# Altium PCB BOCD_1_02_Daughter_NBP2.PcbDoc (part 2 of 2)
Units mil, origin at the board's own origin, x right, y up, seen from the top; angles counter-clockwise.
Board outline 2716.51 x 3188.78 mil, 2 copper layers (Top Layer, Bottom Layer); 52 components, 189 nets, 558 pads, 192 vias.
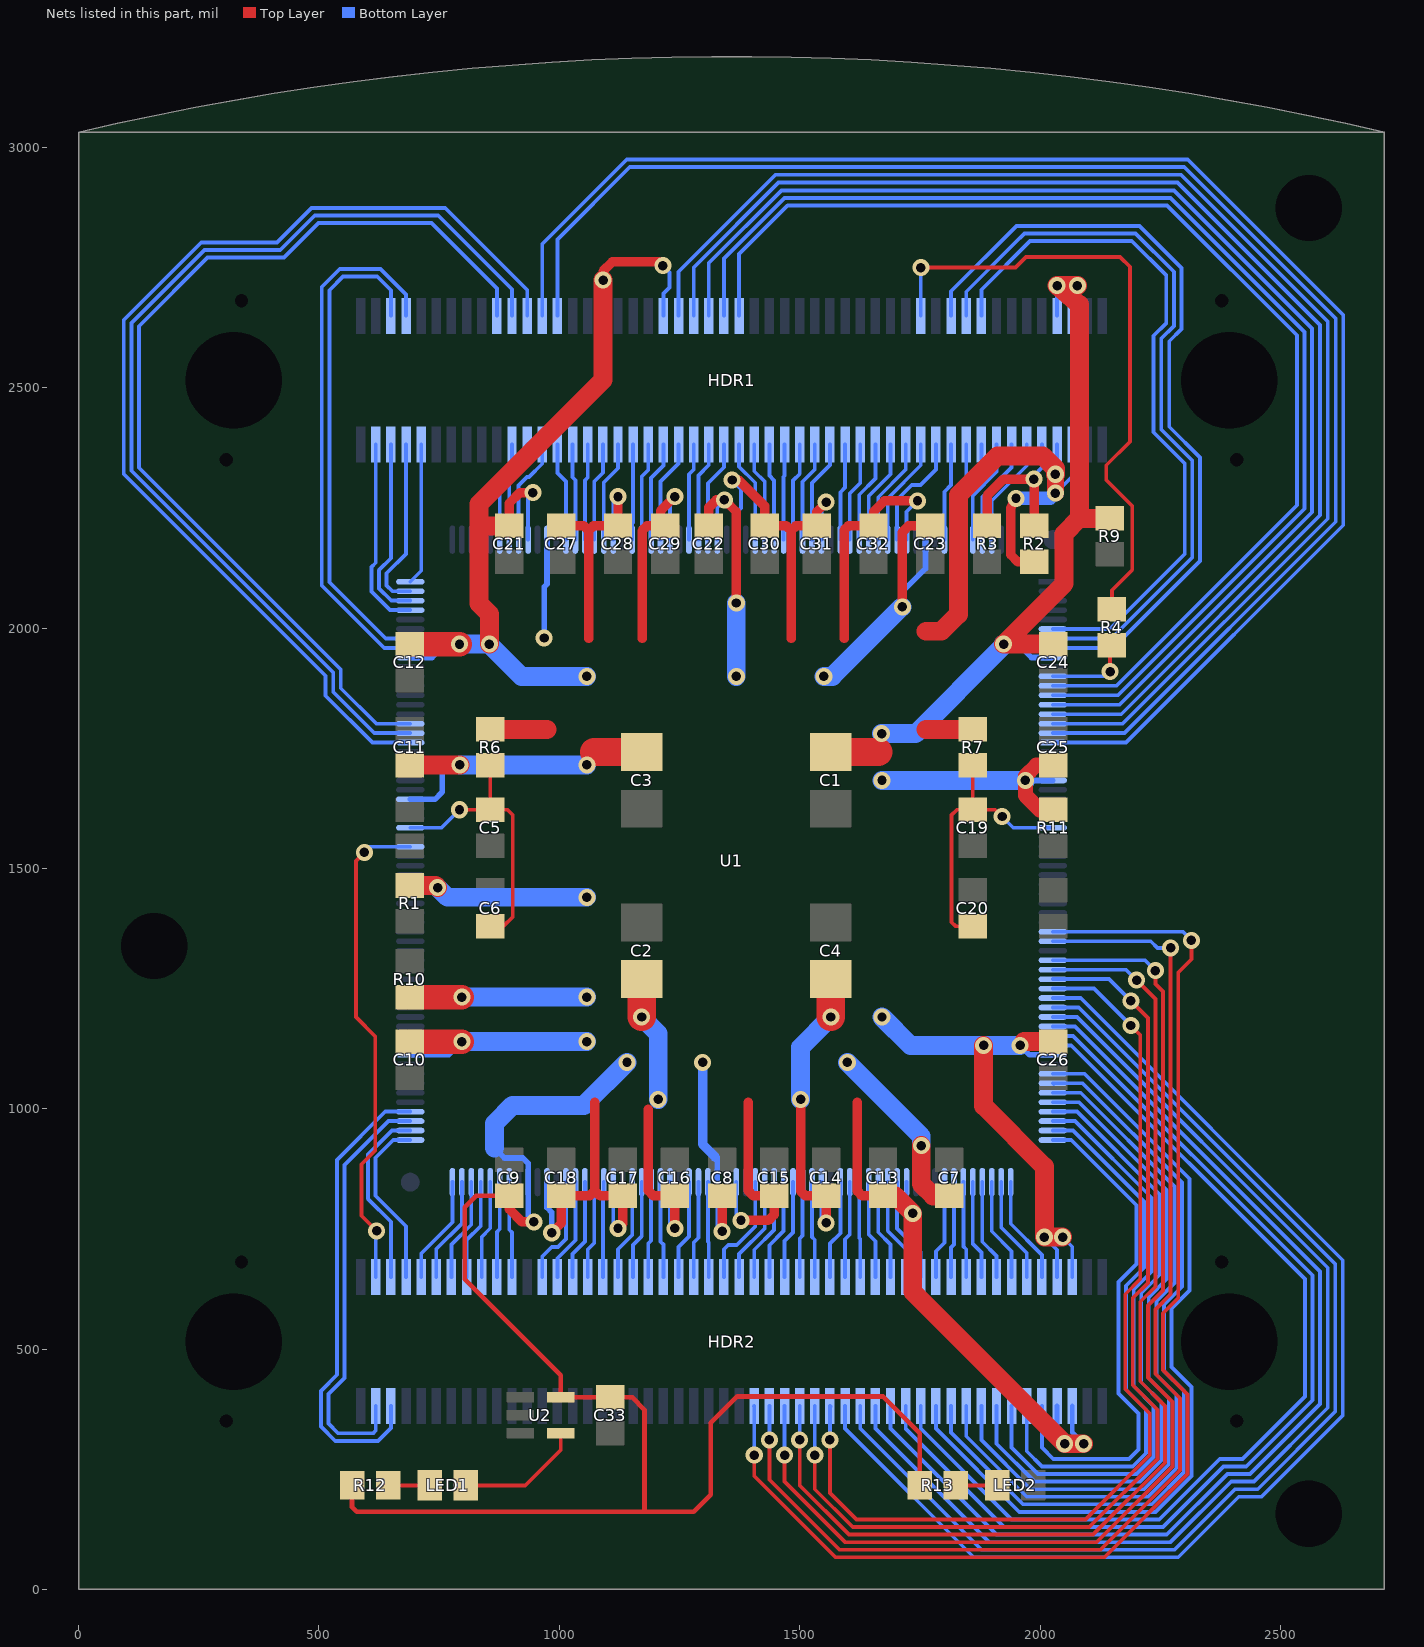
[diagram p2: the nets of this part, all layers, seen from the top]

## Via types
v1: diameter 35.43, hole 19.68, Top Layer to Bottom Layer, 192 vias

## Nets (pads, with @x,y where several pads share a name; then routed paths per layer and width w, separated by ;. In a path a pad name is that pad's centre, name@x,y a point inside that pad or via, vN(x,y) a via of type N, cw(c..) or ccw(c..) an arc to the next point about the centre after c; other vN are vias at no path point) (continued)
IO23: HDR2.53 U1.38 | length 2641.5
  Top Layer w7.87: v1(1405.51,279.53) 1405.51,236.22 1574.8,66.93 2133.86,66.93 2307.09,240.16 2307.09,405.51 2255.91,456.69 2255.91,574.8 2287.4,606.3 2287.4,1283.46 2314.96,1311.02 v1(2314.96,1350.39)
  Bottom Layer w7.87: HDR2.53@1405,381.38 HDR2.53@1405.51,381.89 v1(1405.51,279.53) ; U1.38@2026.57,1368.11 2297.24,1368.11 v1(2314.96,1350.39)
IO24: HDR2.55 U1.39 | length 2508.4
  Top Layer w7.87: v1(1437.01,311.02) 1437.01,228.35 1582.68,82.68 2125.98,82.68 2291.34,248.03 2291.34,397.64 2240.16,448.82 2240.16,582.68 2271.65,614.17 v1(2271.65,1334.65)
  Bottom Layer w7.87: v1(1437.01,311.02) HDR2.55@1437.01,381.89 ; U1.39@2026.57,1348.43 2230.31,1348.43 2244.09,1334.65 v1(2271.65,1334.65)
IO25: HDR2.57 U1.41 | length 2376.8
  Top Layer w7.87: v1(1468.5,279.53) 1468.5,224.41 1594.49,98.43 2118.11,98.43 2275.59,255.91 2275.59,389.76 2224.41,440.94 2224.41,590.55 2255.91,622.05 2255.91,1244.09 2240.16,1259.84 v1(2240.16,1287.4)
  Bottom Layer w7.87: v1(1468.5,279.53) HDR2.57@1468.5,381.89 ; U1.41@2026.57,1309.06 2218.5,1309.06 v1(2240.16,1287.4)
IO26: HDR2.59 U1.42 | length 2267.2
  Top Layer w7.87: v1(1500,311.02) 1500,216.54 1602.36,114.17 2110.24,114.17 2259.84,263.78 2259.84,381.89 2208.66,433.07 2208.66,598.43 2240.16,629.92 2240.16,1228.35 v1(2200.79,1267.72)
  Bottom Layer w7.87: v1(1500,311.02) HDR2.59@1500,381.89 ; U1.42@2026.57,1289.37 2179.13,1289.37 v1(2200.79,1267.72)
IO27: HDR2.61 U1.43 | length 2160
  Top Layer w7.87: v1(1531.5,279.53) 1531.5,208.66 1610.24,129.92 2102.36,129.92 2244.09,271.65 2244.09,374.02 2192.91,425.2 2192.91,606.3 2224.41,637.8 2224.41,1188.98 v1(2188.98,1224.41)
  Bottom Layer w7.87: v1(1531.5,279.53) HDR2.61@1531.5,381.89 ; U1.43@2026.57,1269.69 2143.7,1269.69 v1(2188.98,1224.41)
IO28: HDR2.63 U1.44 | length 2056.4
  Top Layer w7.87: v1(1562.99,311.02) 1562.99,200.79 1618.11,145.67 2094.49,145.67 2228.35,279.53 2228.35,366.14 2177.17,417.32 2177.17,614.17 2208.66,645.67 2208.66,1153.54 v1(2188.98,1173.23)
  Bottom Layer w7.87: v1(1562.99,311.02) HDR2.63@1562.99,381.89 HDR2.63@1563.98,380.91 ; U1.44@2026.57,1250 2112.2,1250 v1(2188.98,1173.23)
IO29: HDR2.65 U1.45 | length 2467.9
  Bottom Layer w7.87: HDR2.65@1594.49,381.89 1594.49,334.65 1862.2,66.93 2287.4,66.93 2413.39,192.91 2460.63,192.91 2629.92,362.2 2629.92,685.04 2084.64,1230.32 U1.45@2026.57,1230.32
IO30: HDR2.67 U1.46 | length 2374.5
  Bottom Layer w7.87: HDR2.67@1625.98,381.89 1625.98,334.65 1877.95,82.68 2279.53,82.68 2405.51,208.66 2452.76,208.66 2614.17,370.08 2614.17,677.17 2080.71,1210.63 U1.46@2026.57,1210.63
IO31: HDR2.69 U1.47 | length 2281.1
  Bottom Layer w7.87: HDR2.69@1657.48,381.89 1657.48,334.65 1893.7,98.43 2271.65,98.43 2397.64,224.41 2444.88,224.41 2598.43,377.95 2598.43,669.29 2076.77,1190.94 U1.47@2026.57,1190.94
IO32: HDR2.71 U1.48 | length 2187.7
  Bottom Layer w7.87: HDR2.71@1688.98,381.89 1688.98,334.65 1909.45,114.17 2263.78,114.17 2389.76,240.16 2437.01,240.16 2582.68,385.83 2582.68,661.42 2072.83,1171.26 U1.48@2026.57,1171.26
IO33: HDR2.73 U1.49 | length 2094.2
  Bottom Layer w7.87: HDR2.73@1720.47,381.89 1720.47,334.64 1925.2,129.92 2255.91,129.92 2381.89,255.91 2429.13,255.91 2566.93,393.7 2566.93,653.54 2068.9,1151.57 U1.49@2026.57,1151.57
IO34: HDR2.75 U1.50 | length 2000.8
  Bottom Layer w7.87: HDR2.75@1751.97,381.89 1751.97,334.65 1940.95,145.67 2248.03,145.67 2374.02,271.65 2421.26,271.65 2551.18,401.57 2551.18,645.67 2064.96,1131.89 U1.50@2026.57,1131.89
IO35: HDR2.77 U1.53 | length 1707.2
  Bottom Layer w7.87: HDR2.77@1783.47,381.89 1783.47,334.65 1956.69,161.42 2240.16,161.42 2314.96,236.22 2314.96,421.26 2273.62,462.6 2273.62,584.65 2311.02,622.05 2311.02,854.33 2092.52,1072.83 U1.53@2026.57,1072.83
JIOA0: HDR1.3 U1.177 | length 406.4
  Bottom Layer w7.87: HDR1.3@618.11,2381.89 618.11,2135.9 609.25,2127.05 609.25,2075.79 647.64,2037.4 U1.177@689.96,2037.4
JIOA1: HDR1.5 U1.178 | length 385.2
  Bottom Layer w7.87: HDR1.5@649.61,2381.89 649.61,2145.13 625,2120.52 625,2082.31 650.22,2057.09 U1.178@689.96,2057.09
JIOA2: HDR1.7 U1.179 | length 364
  Bottom Layer w7.87: HDR1.7@681.1,2381.89 681.1,2154.35 640.75,2114 640.75,2088.83 652.81,2076.77 U1.179@689.96,2076.77
JIOA3: HDR1.9 U1.180 | length 294.8
  Bottom Layer w7.87: U1.180@689.96,2096.46 712.6,2119.09 HDR1.9@712.6,2381.89
JIOB0: HDR1.83 U1.235 | length 213.3
  Bottom Layer w7.87: U1.235@1840.55,2184.06 1840.55,2278.42 1877.95,2315.82 HDR1.83@1877.95,2381.89
JIOB1: HDR1.85 U1.236 | length 218.2
  Bottom Layer w7.87: U1.236@1860.24,2184.06 1860.24,2275.83 1909.45,2325.05 HDR1.85@1909.45,2381.89
JIOB2: HDR1.87 U1.237 | length 223.1
  Bottom Layer w7.87: U1.237@1879.92,2184.06 1879.92,2273.25 1940.95,2334.27 HDR1.87@1940.95,2381.89
JIOB3: HDR1.89 U1.238 | length 228
  Bottom Layer w7.87: U1.238@1899.61,2184.06 1899.61,2264.76 1972.44,2337.6 HDR1.89@1972.44,2381.89
KBCLOCK: HDR1.22 U1.164 | length 2140.4
  Bottom Layer w7.87: U1.164@689.96,1781.5 615.16,1781.5 529.53,1867.13 529.53,1907.34 109.75,2327.12 109.75,2634.61 261.56,2786.42 419.29,2786.42 491.14,2858.27 748.03,2858.27 901.57,2704.72 HDR1.22@901.57,2649.61
KBDATA: HDR1.24 U1.163 | length 2232.5
  Bottom Layer w7.87: U1.163@689.96,1761.81 611.22,1761.81 513.78,1859.25 513.78,1900.82 94,2320.6 94,2641.13 255.04,2802.17 412.77,2802.17 484.62,2874.02 762.8,2874.02 933.07,2703.74 HDR1.24@933.07,2649.61
LCD_BCKL: HDR2.22 U1.114 | length 203.1
  Bottom Layer w7.87: U1.114@897.64,845.47 U1.114@895.67,847.44 895.67,748.28 901.57,742.38 HDR2.22@901.57,649.61
LCD_E: HDR2.26 U1.108 | length 225.7
  Bottom Layer w7.87: HDR2.26@964.57,649.61 964.57,692.91 984.25,712.6 997.05,712.6 1013.78,729.33 U1.108@1013.78,847.44
LED0: HDR2.60 U1.83 | length 200.3
  Bottom Layer w7.87: HDR2.60@1500,649.61 1500,730.32 1505.91,736.22 U1.83@1505.91,847.44
LED1: HDR2.62 U1.82 | length 200.3
  Bottom Layer w7.87: U1.82@1525.59,847.44 1525.59,733.27 1531.5,727.36 HDR2.62@1531.5,649.61
LED2: HDR2.64 U1.79 | length 206.8
  Bottom Layer w7.87: HDR2.64@1562.99,649.61 1562.99,719.49 1584.65,741.14 U1.79@1584.65,847.44
LED3: HDR2.66 U1.78 | length 201.9
  Bottom Layer w7.87: HDR2.66@1594.49,649.61 1594.49,728.71 1604.33,738.56 U1.78@1604.33,847.44
LED4: HDR2.68 U1.77 | length 198.7
  Bottom Layer w7.87: U1.77@1624.02,847.44 1624.02,731.3 1625.98,729.33 HDR2.68@1625.98,649.61
LED5: HDR2.70 U1.76 | length 203.5
  Bottom Layer w7.87: U1.76@1643.7,847.44 1643.7,738.19 1657.48,724.41 HDR2.70@1657.48,649.61
LED6: HDR2.72 U1.75 | length 208.4
  Bottom Layer w7.87: U1.75@1663.39,847.44 1663.39,743.11 1688.98,717.52 HDR2.72@1688.98,649.61
LED7: HDR2.74 U1.74 | length 213.3
  Bottom Layer w7.87: U1.74@1683.07,847.44 1683.07,746.06 1720.47,708.66 HDR2.74@1720.47,649.61
MOUSECLOCK: HDR1.26 U1.18 | length 3251.5
  Bottom Layer w7.87: HDR1.26@964.57,2649.61 964.57,2799.21 1140.1,2974.75 2307.25,2974.75 2630.91,2651.09 2630.91,2213.91 2178.81,1761.81 U1.18@2026.57,1761.81
MOUSEDATA: HDR1.28 U1.17 | length 3164.2
  Bottom Layer w7.87: HDR1.28@996.06,2649.61 996.06,2808.44 1146.63,2959 2300,2959 2615.16,2643.84 2615.16,2221.16 2175.5,1781.5 U1.17@2026.57,1781.5
NetC5_1: C5.1 C6.1 R6.2 U1.154 | length 592.2
  Top Layer w7.87: v1(792.32,1622.05) C5.1@856.3,1622.05 ; C6.1@856.3,1379.92 883.92,1379.92 903,1399 903,1611 891.95,1622.05 C5.1@856.3,1622.05 ; R6.2@856.3,1714.57 C5.1@856.3,1622.05
  Bottom Layer w7.87: U1.154@689.96,1584.65 754.92,1584.65 v1(792.32,1622.05)
NetC19_2: C19.2 C20.2 R7.2 U1.27 | length 593.7
  Top Layer w7.87: C20.2@1860.24,1379.92 1824.08,1379.92 1816,1388 1816,1611 1827.05,1622.05 1906.95,1622.05 v1(1921,1608) ; C19.2@1860.24,1622.05 R7.2@1860.24,1714.57
  Bottom Layer w7.87: v1(1921,1608) 1944.35,1584.65 U1.27@2026.57,1584.65
NetLED1_1: LED1.1 R12.2 | length 86.6
  Top Layer w7.87: R12.2@643.7,216.54 LED1.1@730.32,216.54
NetLED1_2: LED1.2 U2.4 | length 262.9
  Top Layer w7.87: LED1.2@805.12,216.54 929.13,216.54 1002.95,290.35 U2.4@1002.95,324.8
NetLED2_1: LED2.1 R13.2 | length 86.6
  Top Layer w7.87: R13.2@1824.8,216.54 LED2.1@1911.42,216.54
NEXUS_TCK: HDR1.82 U1.7 | length 1557.6
  Bottom Layer w7.87: HDR1.82@1846.46,2649.61 1846.46,2699.8 1947.53,2800.88 1967.52,2820.87 2198.82,2820.87 2278.54,2741.14 2278.54,2628.39 2252,2601.84 2252,2413.73 2316.78,2348.95 2316.78,2146.78 2148.35,1978.35 U1.7@2026.57,1978.35
NEXUS_TDI: HDR1.84 U1.6 | length 1467
  Bottom Layer w7.87: HDR1.84@1877.95,2649.61 1877.95,2703.74 1979.33,2805.12 2190.94,2805.12 2262.8,2733.27 2262.8,2634.91 2236,2608.11 2236,2407.46 2301,2342.46 2301,2154.03 2145,1998.03 U1.6@2026.57,1998.03
NEXUS_TDO: HDR1.76 R4.2 | length 1325.6
  Top Layer w7.87: v1(1751.97,2750) 1949.08,2750 1971.09,2772.01 2166.64,2772.01 2187.01,2751.64 2187.01,2387.8 2137.8,2338.58 2137.8,2308.2 2192,2254 2192,2121.13 2149.61,2078.74 R4.2@2149.61,2039.37
  Bottom Layer w7.87: HDR1.76@1751.97,2649.61 v1(1751.97,2750)
NEXUS_TDO#: R4.1 U1.11 | length 194
  Top Layer w7.87: v1(2145.67,1909.45) R4.1@2145.67,1980.31
  Bottom Layer w7.87: U1.11@2026.57,1899.61 2135.83,1899.61 v1(2145.67,1909.45)
NEXUS_TMS: HDR1.80 U1.8 | length 1650.8
  Bottom Layer w7.87: HDR1.80@1814.96,2649.61 1814.96,2700.79 1950.79,2836.61 2206.69,2836.61 2294.29,2749.02 2294.29,2621.86 2269,2596.57 2269,2419 2333,2355 2333,2139.66 2152,1958.66 U1.8@2026.57,1958.66
RAM0_DATA0: HDR2.42 U1.98 | length 200.3
  Bottom Layer w7.87: U1.98@1210.63,847.44 1210.63,723.43 1216.54,717.52 HDR2.42@1216.54,649.61
RAM0_DATA1: HDR2.40 U1.99 | length 200.3
  Bottom Layer w7.87: HDR2.40@1185.04,649.61 1185.04,719.49 1190.94,725.39 U1.99@1190.94,847.44
RAM0_DATA2: HDR2.38 U1.100 | length 205.2
  Bottom Layer w7.87: HDR2.38@1153.54,649.61 1153.54,716.9 1171.26,734.62 U1.100@1171.26,847.44
RAM0_DATA3: HDR2.36 U1.101 | length 210.1
  Bottom Layer w7.87: HDR2.36@1122.05,649.61 1122.05,707.68 1151.57,737.2 U1.101@1151.57,847.44
RAM0_DATA4: HDR2.34 U1.104 | length 198.7
  Bottom Layer w7.87: HDR2.34@1090.55,649.61 1090.55,810.04 1092.52,812.01 U1.104@1092.52,847.44
RAM0_DATA5: HDR2.32 U1.105 | length 203.5
  Bottom Layer w7.87: HDR2.32@1059.05,649.61 1059.05,707.43 1072.83,721.21 U1.105@1072.83,847.44
RAM0_DATA6: HDR2.30 U1.106 | length 208.4
  Bottom Layer w7.87: HDR2.30@1027.56,649.61 1027.56,698.2 1053.15,723.79 U1.106@1053.15,847.44
RAM0_DATA7: HDR2.28 U1.107 | length 213.3
  Bottom Layer w7.87: HDR2.28@996.06,649.61 996.06,688.98 1033.46,726.38 U1.107@1033.46,847.44
RAM0_OE: HDR1.41 U1.202 | length 208.4
  Bottom Layer w7.87: U1.202@1190.94,2184.06 1190.94,2312.37 1216.54,2337.97 HDR1.41@1216.54,2381.89
RAM0_WE: HDR1.79 U1.233 | length 203.5
  Bottom Layer w7.87: U1.233@1801.18,2184.06 1801.18,2283.59 1814.96,2297.37 HDR1.79@1814.96,2381.89
RAM1_DATA0: HDR1.45 U1.206 | length 201.9
  Bottom Layer w7.87: U1.206@1269.69,2184.06 1269.69,2319.88 1279.53,2329.72 HDR1.45@1279.53,2381.89
RAM1_DATA1: HDR1.49 U1.208 | length 211.7
  Bottom Layer w7.87: U1.208@1309.06,2184.06 1309.06,2301.18 1342.52,2334.65 HDR1.49@1342.52,2381.89
RAM1_DATA2: HDR1.53 U1.214 | length 206.8
  Bottom Layer w7.87: HDR1.53@1405.51,2381.89 1405.51,2326.4 1427.17,2304.75 U1.214@1427.17,2184.06
RAM1_DATA3: HDR1.57 U1.216 | length 198.6
  Bottom Layer w7.87: U1.216@1466.54,2184.06 1466.54,2314.96 1468.5,2316.93 HDR1.57@1468.5,2381.89
RAM1_DATA4: HDR1.55 U1.215 | length 201.9
  Bottom Layer w7.87: HDR1.55@1437.01,2381.89 1437.01,2317.18 1446.85,2307.34 U1.215@1446.85,2184.06
RAM1_DATA5: HDR1.51 U1.213 | length 211.7
  Bottom Layer w7.87: HDR1.51@1374.02,2381.89 1374.02,2335.63 1407.48,2302.17 U1.213@1407.48,2184.06
RAM1_DATA6: HDR1.47 U1.207 | length 206.8
  Bottom Layer w7.87: U1.207@1289.37,2184.06 1289.37,2317.3 1311.02,2338.95 HDR1.47@1311.02,2381.89
RAM1_DATA7: HDR1.43 U1.203 | length 213.3
  Bottom Layer w7.87: U1.203@1210.63,2184.06 1210.63,2305.12 1248.03,2342.52 HDR1.43@1248.03,2381.89
RAM1_OE: HDR1.39 U1.201 | length 203.5
  Bottom Layer w7.87: U1.201@1171.26,2184.06 1171.26,2314.96 1185.04,2328.74 HDR1.39@1185.04,2381.89
RAM1_WE: HDR1.61 U1.218 | length 208.4
  Bottom Layer w7.87: U1.218@1505.91,2184.06 1505.91,2304.5 1531.5,2330.09 HDR1.61@1531.5,2381.89
RAM_ADDR0: HDR1.21 U1.186 | length 208.4
  Bottom Layer w7.87: U1.186@875.98,2184.06 875.98,2308.64 901.57,2334.23 HDR1.21@901.57,2381.89
RAM_ADDR1: HDR1.25 U1.188 | length 220.6
  Bottom Layer w7.87: U1.188@915.35,2184.06 915.35,2296.79 932.97,2314.4 936.97,2314.4 964.57,2342 HDR1.25@964.57,2381.89
RAM_ADDR2: HDR1.29 U1.194 | length 200.3
  Bottom Layer w7.87: HDR1.29@1027.56,2381.89 1027.56,2313.61 1033.46,2307.7 U1.194@1033.46,2184.06
RAM_ADDR3: HDR1.33 U1.196 | length 205.2
  Bottom Layer w7.87: U1.196@1072.83,2184.06 1072.83,2305.38 1090.55,2323.1 HDR1.33@1090.55,2381.89
RAM_ADDR4: HDR1.65 U1.222 | length 201.9
  Bottom Layer w7.87: U1.222@1584.65,2184.06 1584.65,2282.61 1594.49,2292.46 HDR1.65@1594.49,2381.89
RAM_ADDR5: HDR1.69 U1.224 | length 211.7
  Bottom Layer w7.87: U1.224@1624.02,2184.06 1624.02,2277.44 1657.48,2310.91 HDR1.69@1657.48,2381.89
RAM_ADDR6: HDR1.73 U1.226 | length 221.5
  Bottom Layer w7.87: U1.226@1663.39,2184.06 1663.39,2272.27 1720.47,2329.36 HDR1.73@1720.47,2381.89
RAM_ADDR7: HDR1.77 U1.228 | length 241.8
  Bottom Layer w7.87: U1.228@1702.76,2184.06 1702.76,2266.93 1733.27,2297.44 1751.18,2297.44 1783.47,2329.73 HDR1.77@1783.47,2381.89
RAM_ADDR8: HDR1.75 U1.227 | length 226.4
  Bottom Layer w7.87: U1.227@1683.07,2184.06 1683.07,2269.68 1751.97,2338.58 HDR1.75@1751.97,2381.89
RAM_ADDR9: HDR1.71 U1.225 | length 216.6
  Bottom Layer w7.87: U1.225@1643.7,2184.06 1643.7,2274.86 1688.98,2320.13 HDR1.71@1688.98,2381.89
RAM_ADDR10: HDR1.67 U1.223 | length 206.8
  Bottom Layer w7.87: U1.223@1604.33,2184.06 1604.33,2280.03 1625.98,2301.68 HDR1.67@1625.98,2381.89
RAM_ADDR11: HDR1.63 U1.219 | length 213.3
  Bottom Layer w7.87: U1.219@1525.59,2184.06 1525.59,2301.91 1562.99,2339.32 HDR1.63@1562.99,2381.89
RAM_ADDR12: HDR1.59 U1.217 | length 203.5
  Bottom Layer w7.87: U1.217@1486.22,2184.06 1486.22,2307.09 1500,2320.87 HDR1.59@1500,2381.89
RAM_ADDR13: HDR1.35 U1.197 | length 210.1
  Bottom Layer w7.87: U1.197@1092.52,2184.06 1092.52,2302.79 1122.05,2332.32 HDR1.35@1122.05,2381.89
RAM_ADDR14: HDR1.31 U1.195 | length 200.3
  Bottom Layer w7.87: U1.195@1053.15,2184.06 1053.15,2307.1 1059.05,2313 HDR1.31@1059.05,2381.89
RAM_ADDR15: HDR1.27 U1.193 | length 205.2
  Bottom Layer w7.87: HDR1.27@996.06,2381.89 996.06,2322.83 1013.78,2305.12 U1.193@1013.78,2184.06
RAM_ADDR16: HDR1.23 U1.187 | length 213.3
  Bottom Layer w7.87: U1.187@895.67,2184.06 895.67,2302.6 933.07,2340 HDR1.23@933.07,2381.89
RAM_CS: HDR1.37 U1.200 | length 198.7
  Bottom Layer w7.87: U1.200@1151.57,2184.06 1151.57,2217.52 1153.54,2219.49 HDR1.37@1153.54,2381.89
RED0: HDR1.6 U1.174 | length 1028.9
  Bottom Layer w7.87: HDR1.6@649.61,2649.61 649.61,2702.76 621.06,2731.3 550.2,2731.3 521.65,2702.76 521.65,2095.47 638.78,1978.35 U1.174@689.96,1978.35
RED1: HDR1.8 U1.173 | length 1115.9
  Bottom Layer w7.87: HDR1.8@681.1,2649.61 681.1,2693.9 627.95,2747.05 543.31,2747.05 505.91,2709.65 505.91,2088.58 635.83,1958.66 U1.173@689.96,1958.66
REF_CLK: HDR2.4 U1.152 | length 1034.6
  Top Layer w7.87: v1(594.49,1533.46) 576.77,1515.75 576.77,1190.77 617,1150.54 617,913 588.5,884.5 588.5,777.65 v1(620.08,746.06)
  Bottom Layer w7.87: v1(594.49,1533.46) 604.33,1545.28 U1.152@689.96,1545.28 ; HDR2.4@618.11,649.61 618.11,744.09 v1(620.08,746.06)
SCL: HDR2.5 U1.124 | length 978.3
  Bottom Layer w7.87: HDR2.5@649.61,381.89 649.61,335.63 622.87,308.89 533.88,308.89 503.94,338.83 503.94,413.12 537.4,446.58 537.4,893.7 637.79,994.09 U1.124@689.96,994.09
SDA: HDR2.3 U1.123 | length 886.7
  Bottom Layer w7.87: HDR2.3@618.11,381.89 618.11,330.71 612.2,324.8 540.24,324.8 519.68,345.36 519.68,406.6 553.15,440.06 553.15,882.87 644.69,974.41 U1.123@689.96,974.41
SP0: HDR2.79 U1.54 | length 1621.1
  Bottom Layer w7.87: HDR2.79@1814.96,381.89 1814.96,326.77 1964.57,177.17 2232.28,177.17 2299.21,244.09 2299.21,413.39 2257.87,454.72 2257.87,592.52 2295.28,629.92 2295.28,846.46 2088.58,1053.15 U1.54@2026.57,1053.15 U1.54@2028.54,1051.18
SP1: HDR2.81 U1.55 | length 1529.6
  Bottom Layer w7.87: HDR2.81@1846.46,381.89 1846.46,318.9 1972.44,192.91 2224.41,192.91 2283.46,251.97 2283.46,405.51 2242.13,446.85 2242.13,600.39 2279.53,637.8 2279.53,838.58 2084.65,1033.46 U1.55@2026.57,1033.46
SP2: HDR2.83 U1.56 | length 1440.7
  Bottom Layer w7.87: HDR2.83@1877.95,381.89 1877.95,311.02 1980.32,208.66 2216.54,208.66 2267.72,259.84 2267.72,397.64 2226.38,438.98 2226.38,608.27 2263.78,645.67 2263.78,830.71 2080.71,1013.78 U1.56@2026.57,1013.78
SP3: HDR2.85 U1.57 | length 1351.9
  Bottom Layer w7.87: HDR2.85@1909.45,381.89 1909.45,303.15 1988.19,224.41 2208.66,224.41 2251.97,267.72 2251.97,389.76 2210.63,431.1 2210.63,616.14 2248.03,653.54 2248.03,822.83 2076.77,994.09 U1.57@2026.57,994.09
SP4: HDR2.87 U1.58 | length 1263.1
  Bottom Layer w7.87: HDR2.87@1940.95,381.89 1940.95,295.27 1996.06,240.16 2200.79,240.16 2236.22,275.59 2236.22,381.89 2194.88,423.23 2194.88,624.02 2232.28,661.42 2232.28,814.96 2072.83,974.41 U1.58@2026.57,974.41
SP5: HDR2.89 U1.59 | length 1174.3
  Bottom Layer w7.87: HDR2.89@1972.44,381.89 1972.44,287.4 2003.94,255.91 2192.91,255.91 2220.47,283.46 2220.47,374.02 2179.13,415.35 2179.13,631.89 2216.54,669.29 2216.54,807.09 2068.9,954.72 U1.59@2026.57,954.72
SP6: HDR2.91 U1.60 | length 1076.3
  Bottom Layer w7.87: HDR2.91@2003.94,381.89 2003.94,295.28 2027.56,271.65 2185.04,271.65 2204.72,291.34 2204.72,366.14 2163.39,407.48 2163.39,639.76 2200.79,677.17 2200.79,799.21 2064.96,935.04 U1.60@2026.57,935.04
SP7: HDR2.92 U1.61 | length 224.7
  Bottom Layer w7.87: U1.61@1938.98,847.44 1938.98,760.83 2003.94,695.87 HDR2.92@2003.94,649.61
SP8: HDR2.90 U1.62 | length 219.9
  Bottom Layer w7.87: U1.62@1919.29,847.44 1919.29,752.95 1972.44,699.8 HDR2.90@1972.44,649.61
SP9: HDR2.88 U1.63 | length 215
  Bottom Layer w7.87: U1.63@1899.61,847.44 1899.61,745.08 1940.95,703.74 HDR2.88@1940.95,649.61
SP10: HDR2.86 U1.64 | length 210.1
  Bottom Layer w7.87: U1.64@1879.92,847.44 1879.92,723.43 1909.45,693.9 HDR2.86@1909.45,649.61
SP11: HDR2.84 U1.65 | length 205.2
  Bottom Layer w7.87: U1.65@1860.24,847.44 1860.24,718.5 1877.95,700.79 HDR2.84@1877.95,649.61
SP12: HDR2.82 U1.66 | length 200.3
  Bottom Layer w7.87: U1.66@1840.55,847.44 1840.55,713.58 1846.46,707.68 HDR2.82@1846.46,649.61
SP13: HDR2.80 U1.67 | length 200.3
  Bottom Layer w7.87: HDR2.80@1814.96,649.61 1814.96,711.61 1820.87,717.52 U1.67@1820.87,847.44
SP14: HDR2.78 U1.68 | length 205.2
  Bottom Layer w7.87: HDR2.78@1783.47,649.61 1783.47,703.74 1801.18,721.46 U1.68@1801.18,847.44
SP15: HDR2.76 U1.73 | length 218.2
  Bottom Layer w7.87: U1.73@1702.76,847.44 1702.76,750.98 1751.97,701.77 HDR2.76@1751.97,649.61
SPI_CLK: HDR1.46 U1.15 | length 2723.1
  Bottom Layer w7.87: HDR1.46@1279.53,2649.61 1279.53,2750.37 1456.16,2927 2286,2927 2582.68,2630.32 2582.68,2234.68 2168.87,1820.87 U1.15@2026.57,1820.87
SPI_DIN: HDR1.44 U1.16 | length 2810.6
  Bottom Layer w7.87: HDR1.44@1248.03,2649.61 1248.03,2741.14 1449.89,2943 2293,2943 2598.43,2637.57 2598.43,2227.43 2172.18,1801.18 U1.16@2026.57,1801.18
SPI_DOUT: HDR1.50 U1.13 | length 2546.5
  Bottom Layer w7.87: HDR1.50@1342.52,2649.61 1342.52,2768.82 1468.45,2894.75 2271.25,2894.75 2550.2,2615.8 2550.2,2248.2 2162.24,1860.24 U1.13@2026.57,1860.24
SPI_MODE: HDR1.52 U1.12 | length 2459.5
  Bottom Layer w7.87: HDR1.52@1374.02,2649.61 1374.02,2778.04 1474.97,2879 2264.45,2879 2534.45,2609 2534.45,2255.45 2158.92,1879.92 U1.12@2026.57,1879.92
SPI_SEL: HDR1.48 U1.14 | length 2633.8
  Bottom Layer w7.87: HDR1.48@1311.02,2649.61 1311.02,2759.59 1461.93,2910.5 2278.5,2910.5 2565.94,2623.06 2565.94,2240.94 2165.55,1840.55 U1.14@2026.57,1840.55
SW0: HDR2.44 U1.95 | length 206.8
  Bottom Layer w7.87: HDR2.44@1248.03,649.61 1248.03,712.6 1269.69,734.25 U1.95@1269.69,847.44
SW1: HDR2.46 U1.94 | length 201.9
  Bottom Layer w7.87: HDR2.46@1279.53,649.61 1279.53,721.82 1289.37,731.67 U1.94@1289.37,847.44
SW2: HDR2.48 U1.93 | length 198.7
  Bottom Layer w7.87: U1.93@1309.06,847.44 1309.06,723.43 1311.02,721.46 HDR2.48@1311.02,649.61
SW3: HDR2.50 U1.88 | length 235.1
  Bottom Layer w7.87: HDR2.50@1342.52,649.61 1342.52,707.68 1351.38,716.54 1369.09,716.54 1407.48,754.92 U1.88@1407.48,847.44
SW4: HDR2.52 U1.87 | length 219.9
  Bottom Layer w7.87: HDR2.52@1374.02,649.61 1374.02,697.83 1427.17,750.98 U1.87@1427.17,847.44
SW5: HDR2.54 U1.86 | length 215
  Bottom Layer w7.87: HDR2.54@1405.51,649.61 1405.51,706.69 1446.85,748.03 U1.86@1446.85,847.44
SW6: HDR2.56 U1.85 | length 210.1
  Bottom Layer w7.87: HDR2.56@1437.01,649.61 1437.01,715.92 1466.54,745.45 U1.85@1466.54,847.44
SW7: HDR2.58 U1.84 | length 205.2
  Bottom Layer w7.87: HDR2.58@1468.5,649.61 1468.5,725.14 1486.22,742.86 U1.84@1486.22,847.44
SWC0: HDR2.18 U1.116 | length 205.2
  Bottom Layer w7.87: HDR2.18@838.58,649.61 838.58,733.58 856.3,751.3 U1.116@856.3,847.44
SWC1: HDR2.16 U1.117 | length 210.1
  Bottom Layer w7.87: HDR2.16@807.09,649.61 807.09,726.78 836.61,756.3 U1.117@836.61,847.44
SWC2: HDR2.14 U1.118 | length 215
  Bottom Layer w7.87: HDR2.14@775.59,649.61 775.59,717.55 816.93,758.89 U1.118@816.93,847.44
SWC3: HDR2.6 U1.122 | length 383.5
  Bottom Layer w7.87: HDR2.6@649.61,649.61 649.61,765 602,812.61 602,904.78 651.94,954.72 U1.122@689.96,954.72
SWR0: HDR2.20 U1.115 | length 200.3
  Bottom Layer w7.87: HDR2.20@870.08,649.61 870.08,743.67 875.98,749.58 U1.115@875.98,847.44
SWR1: HDR2.12 U1.119 | length 219.9
  Bottom Layer w7.87: HDR2.12@744.09,649.61 744.09,708.32 797.24,761.48 U1.119@797.24,847.44
SWR2: HDR2.10 U1.120 | length 224.7
  Bottom Layer w7.87: HDR2.10@712.6,649.61 712.6,699.1 777.56,764.06 U1.120@777.56,847.44
SWR3: HDR2.8 U1.121 | length 362.3
  Bottom Layer w7.87: HDR2.8@681.1,649.61 681.1,755.78 617.75,819.13 617.75,898.26 654.53,935.04 U1.121@689.96,935.04
TEST: HDR1.81 U1.234 | length 208.4
  Bottom Layer w7.87: U1.234@1820.87,2184.06 1820.87,2281.01 1846.46,2306.6 HDR1.81@1846.46,2381.89
VCC: C1.1 C3.1 C7.1 C8.1 C9.1 C10.1 C11.1 C12.1 C21.2 C22.2 C23.2 C24.2 C25.2 C26.2 C33.1 HDR1.34 HDR1.42 HDR1.94 HDR1.96 HDR2.94 HDR2.96 R1.1 R9.1 R10.1 R11.1 R12.1 R13.1 U1.9 U1.22 U1.51 U1.70 U1.92 U1.112 U1.130 U1.157 U1.172 U1.189 U1.209 U1.231 U2.5 | length 12506.2
  Top Layer w9.84: R12.1@568.9,216.54 568.9,171.26 578.74,161.42 1279.53,161.42 1314.96,196.85 1314.96,346.46 1370.08,401.57 1673.23,401.57 1750,324.8 R13.1@1750,216.54 ; C9.1@895.67,818.9 826.77,818.9 803.15,795.28 803.15,645.67 1002.95,445.87 U2.5@1002.95,399.61 1151.57,399.61 1177.17,374.02 1177.17,161.42
  Top Layer w19.68: C9.1@895.67,818.9 895.67,791.34 922.24,764.76 v1(946.85,764.76) ; C21.2@895.67,2212.6 895.67,2259.67 918,2282 v1(945,2282) ; v1(1091,2724) 1091,2742.8 1110,2761.8 1207.68,2761.8 v1(1215.54,2753.95) ; C22.2@1311.02,2212.6 1311.02,2250.98 1326.77,2266.73 v1(1343.5,2266.73) 1368.11,2242.13 v1(1368.11,2052.17) ; v1(1338.58,745.08) C8.1@1338.58,818.9 ; v1(1713.58,2044.29) 1713.58,2199.8 1726.38,2212.6 C23.2@1771.65,2212.6
  Top Layer w31.5: R11.1@2027.56,1622.05 1999.02,1622.05 1969.49,1651.57 1969.49,1691.93 1992.13,1714.57 C25.2@2027.56,1714.57
  Top Layer w39.37: R1.1@688.98,1464.57 742.43,1464.57 v1(747,1460) ; C11.1@688.98,1714.57 689.96,1715.55 v1(793.31,1715.55) ; 832.68,2212.6 C21.2@895.67,2212.6 ; v1(854.33,1966.54) 854.33,2029.53 832.68,2051.18 832.68,2258 1091,2516.32 v1(1091,2724) ; v1(1752.95,923.22) 1752.95,843.5 1777.56,818.9 C7.1@1811.02,818.9 ; v1(1882.7,1131.75) 1882.7,1006.05 2009,879.75 v1(2009,733) v1(2047,733) ; v1@1966.54,1139.76 C26.2@2027.56,1139.76 ; C24.2@2027.56,1966.54 v1(1924.21,1966.54) 2050,2092.32 2050,2148 2050,2196 2082,2228 ; v1(2077.76,2712.6) v1(2035.43,2712.6) 2082,2673 2082,2228 ; R9.1@2145,2228.4 2082,2228
  Top Layer w51.18: C10.1@688.98,1139.76 v1(797.24,1139.76) ; R10.1@688.98,1232.28 v1(797.24,1232.28) ; C12.1@688.98,1966.54 v1(792.32,1966.54)
  Top Layer w59.06: 1072.83,1742.13 C3.1@1171.26,1742.13 ; C1.1@1564.96,1742.13 1663.38,1742.13
  Bottom Layer w7.87: U1.189@935.04,2184.06 935.04,2272.04 v1(945,2282) ; HDR1.34@1090.55,2649.61 1090.55,2729.33 v1(1091,2724) ; v1(1215.54,2753.95) 1229.33,2740.16 1229.33,2708.66 1216.54,2695.87 HDR1.42@1216.54,2649.61 ; U1.92@1328.74,847.44 1328.74,754.92 v1(1338.58,745.08) ; U1.209@1328.74,2184.06 1328.74,2251.97 v1(1343.5,2266.73) ; v1(2009,733) 2035.43,706.57 HDR2.94@2035.43,649.61 ; HDR1.94@2035.43,2649.61 v1(2035.43,2712.6) ; v1(2047,733) 2066.93,713.07 HDR2.96@2066.93,649.61 ; HDR1.96@2066.93,2649.61 2066.93,2701.77 v1(2077.76,2712.6)
  Bottom Layer w11.81: U1.130@689.96,1112.2 769.69,1112.2 v1(797.24,1139.76) ; U1.157@689.96,1643.7 741.14,1643.7 756.3,1658.86 756.3,1702.16 769.68,1715.55 v1(793.31,1715.55) ; U1.172@689.96,1938.98 735.24,1938.98 762.8,1966.54 v1(792.32,1966.54) ; 865.25,918.4 886.01,897.64 924.21,897.64 935.04,886.81 U1.112@935.04,847.44 935.04,776.57 v1(946.85,764.76) ; 1324.8,899.17 1328.74,895.23 U1.92@1328.74,847.44 ; v1(1713.58,2044.29) 1713.58,2075.78 1761.81,2124.01 U1.231@1761.81,2184.06 ; v1(1752.95,923.22) 1761.81,914.37 U1.70@1761.81,847.44 ; v1(1924.21,1966.54) 1954.72,1966.54 1982.28,1938.98 U1.9@2026.57,1938.98 ; v1(1958.66,1131.89) 1978.35,1112.2 U1.51@2026.57,1112.2 ; v1(1969.49,1683.07) U1.22@2026.57,1683.07
  Bottom Layer w19.68: v1(1298.23,1096.46) 1298.23,925.74 1324.8,899.17
  Bottom Layer w39.37: v1(747,1460) 767,1440 v1@1057,1440 ; v1(792.32,1966.54) v1(854.33,1966.54) 921.26,1899.61 v1(1057.09,1899.61) ; v1(793.31,1715.55) v1(1057.09,1715.55) ; v1(797.24,1139.76) v1(1057.09,1139.76) ; v1(797.24,1232.28) v1(1057.09,1232.28) ; 865.25,918.4 865.25,969.58 902.56,1006.89 1051.18,1006.89 v1(1140.75,1096.46) ; v1(1368.11,1899.61) v1(1368.11,2052.17) ; v1(1550.2,1899.61) 1567.91,1899.61 v1@1712.6,2044.29 ; v1(1599.41,1096.46) 1752.95,942.91 v1(1752.95,923.22) ; v1(1670.28,1780.51) 1741.14,1780.51 1919.29,1958.66 v1(1924.21,1966.54) ; v1(1671.26,1190.94) 1730.31,1131.89 v1(1882.7,1131.75) v1(1958.66,1131.89) ; v1(1671.26,1683.07) v1(1969.49,1683.07)
  other v1: 1057.09,1440
VCCINT: C2.1 C4.1 C13.1 C14.1 C15.1 C16.1 C17.1 C18.1 C27.2 C28.2 C29.2 C30.2 C31.2 C32.2 HDR1.93 HDR1.95 HDR2.93 HDR2.95 R2.1 R6.1 R7.1 U1.72 U1.81 U1.90 U1.97 U1.103 U1.110 U1.191 U1.198 U1.204 U1.211 U1.220 U1.229 | length 7368.2
  Top Layer w19.68: v1(984.25,742.13) 1003.94,761.81 C18.1@1003.94,818.9 1062.99,818.9 1073.82,829.72 ; C27.2@1003.94,2212.6 1051.18,2212.6 1061.02,2202.76 ; 1061.02,1978.35 1061.02,2202.76 ; 1073.82,1013.78 1073.82,829.72 ; v1(1122.05,750.98) 1131.89,760.83 C17.1@1131.89,818.9 1084.65,818.9 1073.82,829.72 ; v1(1122.05,2273.62) C28.2@1122.05,2212.6 1070.87,2212.6 1061.02,2202.76 ; 1172.24,1978.35 1172.24,2202.76 1182.09,2212.6 C29.2@1210.63,2212.6 ; 1185.04,999.02 1185.04,829.72 1195.87,818.9 C16.1@1240.16,818.9 v1(1240.16,750.98) ; C29.2@1220.47,2212.6 C29.2@1210.63,2212.6 ; v1(1240.16,2273.62) 1210.63,2244.09 C29.2@1210.63,2212.6 ; v1(1359.25,2308.07) 1373.03,2308.07 1427.17,2253.94 C30.2@1427.17,2212.6 1472.44,2212.6 1482.28,2202.76 ; v1(1377.95,767.72) 1435.04,767.72 1446.85,779.53 C15.1@1446.85,818.9 1403.54,818.9 1392.72,829.72 1392.72,1013.78 ; 1482.28,1978.35 1482.28,2202.76 ; v1(1501.96,1019.69) 1501.97,828.74 1511.81,818.9 C14.1@1555.12,818.9 v1(1555.12,762.8) ; v1(1555.12,2261.81) 1535.43,2242.13 C31.2@1535.43,2212.6 1492.13,2212.6 1482.28,2202.76 ; 1592.52,1978.35 1592.52,2203.74 1601.38,2212.6 C32.2@1653.54,2212.6 1653.54,2242.13 1676.18,2264.76 v1(1745.08,2264.76) ; 1620.08,1013.78 1620.08,828.74 1629.92,818.9 C13.1@1673.23,818.9 ; v1(1950,2270) 1938.98,2250 1938.98,2152.56 1953.74,2137.8 R2.1@1988.19,2137.8
  Top Layer w35.43: v1(2032,2280.63) v1(2032,2320)
  Top Layer w39.37: R6.1@856.3,1789.37 974.41,1789.37 ; C13.1@1673.23,818.9 1698.82,818.9 v1(1735.24,782.48) 1735.24,619.09 v1(2051.18,303.15) v1(2090.55,303.15) ; 1762.8,1789.37 R7.1@1860.24,1789.37 ; 1762.81,1993.44 1795,1993.44 1830,2028.44 1830,2276.45 1911.81,2358.26 2005.74,2358.26 2032,2332 v1(2032,2320)
  Top Layer w59.06: v1(1171.26,1190.94) C2.1@1171.26,1269.69 ; v1(1564.96,1190.94) C4.1@1564.96,1269.69
  Bottom Layer w7.87: U1.103@1112.2,847.44 1112.2,760.83 v1(1122.05,750.98) ; U1.198@1112.2,2184.06 1112.2,2263.78 v1(1122.05,2273.62) ; U1.97@1230.32,847.44 1230.31,760.83 v1(1240.16,750.98) ; U1.204@1230.32,2184.06 1230.31,2263.78 v1(1240.16,2273.62) ; v1(1359.25,2308.07) 1377.95,2289.37 1377.95,2250 1368.11,2240.16 U1.211@1368.11,2184.06 ; U1.90@1368.11,847.44 1368.11,777.56 v1(1377.95,767.72) ; U1.81@1545.28,847.44 1545.28,772.64 v1(1555.12,762.8) ; U1.220@1545.28,2184.06 1545.28,2251.97 v1(1555.12,2261.81) ; U1.72@1722.44,847.44 1722.44,796.26 v1(1735.24,782.48) ; U1.229@1722.44,2184.06 1722.44,2242.13 v1(1745.08,2264.76) ; v1(2032,2280.63) 2066.93,2315.56 HDR1.95@2066.93,2381.89 ; HDR1.93@2035.43,2381.89 v1@2036,2320
  Bottom Layer w9.84: HDR2.93@2035.43,381.89 2035.43,318.9 v1(2051.18,303.15) ; HDR2.95@2066.93,381.89 2066.93,326.77 v1(2090.55,303.15)
  Bottom Layer w11.81: v1(968.5,1979.33) 968.5,2085.76 974.41,2091.67 U1.191@974.41,2184.06 ; U1.110@974.41,847.44 974.41,794.29 984.25,784.45 v1(984.25,742.13)
  Bottom Layer w27.56: v1(1950,2270) 2021.37,2270 v1(2032,2280.63)
  Bottom Layer w39.37: v1(1171.26,1190.94) 1205.71,1156.5 v1(1205.71,1019.69) ; v1(1501.96,1019.69) 1501.96,1127.95 v1(1564.96,1190.94)
VDRIVE: HDR1.20 U1.165 | length 2049
  Bottom Layer w7.87: U1.165@689.96,1801.18 619.09,1801.18 545.28,1875 545.28,1913.87 125.5,2333.65 125.5,2628.08 268.08,2770.67 427.17,2770.67 499.02,2842.52 734.25,2842.52 870.08,2706.69 HDR1.20@870.08,2649.61
VREF: HDR1.91 R2.2 R3.1 | length 351.3
  Top Layer w19.68: R3.1@1889.76,2212.6 1889.76,2275.59 1924.21,2310.04 v1(1987,2310) 1988.19,2308.81 R2.2@1988.19,2212.6
  Bottom Layer w7.87: v1@1987,2317 2003.94,2333.94 HDR1.91@2003.94,2381.89
  Bottom Layer w9.06: v1(1987,2310) v1@1987,2317
pads on no net: HDR1.56 HDR1.MH1 HDR1.MH2 HDR1.MH3 HDR1.MH4 HDR1.MH5 HDR1.MH6 HDR2.MH1 HDR2.MH2 HDR2.MH3 HDR2.MH4 HDR2.MH5 HDR2.MH6 U1.19 U1.20 U1.21 U1.24 U1.32 U1.37 U1.162 U1.239 U1.240 U1.FID1 U1.FID2 U2.1

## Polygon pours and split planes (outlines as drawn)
GND on Top Layer "Top Layer-GND" (solid, remove dead copper, pour order 1000): 2718.8,3191.24 2719.73,3188.98 2719.73,0 2718.8,-2.26 2716.54,-3.2 0,-3.2 -2.26,-2.26 -3.2,0 -3.2,3188.98 -2.26,3191.24 0,3192.17 2716.54,3192.17
GND on Bottom Layer "Bottom Layer-GND" (solid, remove dead copper, pour order 1001): 2718.8,3191.24 2719.73,3188.98 2719.73,0 2718.8,-2.26 2716.54,-3.2 0,-3.2 -2.26,-2.26 -3.2,0 -3.2,3188.98 -2.26,3191.24 0,3192.17 2716.54,3192.17

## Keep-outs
Top Layer:
  lines w31.5: 0,0 2716.54,0
Keep-Out Layer:
  lines w31.5: 0,0 555.12,0 559.06,-3.94 1039.37,-3.94 1043.31,0 2716.54,0 2716.54,3031.5 ccw(c1358.27,-2748.05) 0.02,3031.5 0,0

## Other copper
Top Layer:
  rectangle net VCCINT: 941.93,994.09 1006.89,1955.71
  rectangle net VCCINT: 1002.95,994.09 1780.51,1050.2
  rectangle net VCCINT: 941.93,1946.85 1779.53,2013.78
  rectangle net VCCINT: 1721.46,1018.7 1780.51,1963.58
  rectangle net VCC: 1027.56,1069.88 1104.33,1926.18
  rectangle net VCC: 1080.71,1069.88 1698.82,1139.76
  rectangle net VCC: 1070.87,1823.82 1698.82,1926.18
  rectangle net VCC: 1630.91,1116.14 1698.82,1878.94

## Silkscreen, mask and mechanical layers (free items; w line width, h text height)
Bottom Overlay:
  drawing of 850 lines, arcs and shapes, not listed
  text "REV 1.02" at 1874.02,3011.8 h51.18
  text "NBP2" at 2145.67,3011.8 h51.18
  text "1" at 550,2300 h39.37
  text "1" at 560,300 h39.37
PCB Boundary:
  the board outline again, w9.84
  text "PCB boundary coincides with centre-line of tracks" at 0,-472.44 h29.53
Gerber ID:
  text ".Layer_Name" at 0,-236.22 h29.53
Printout ID:
  text ".Printout_Name" at 0,-393.7 h29.53
Drill Drawing:
  text ".Legend" at 0,-314.96 h29.53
